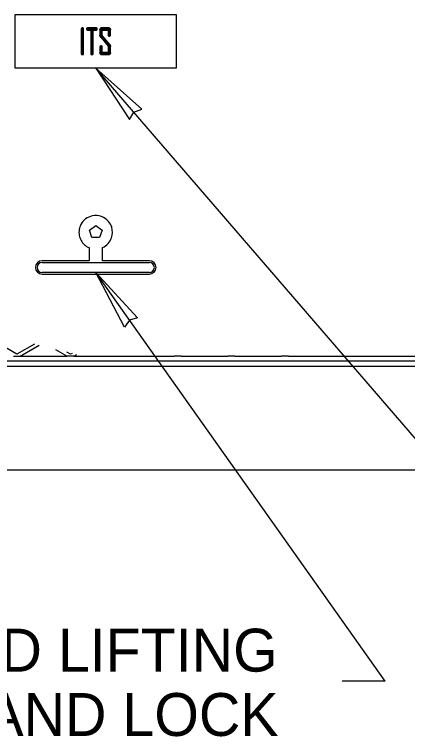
# Model space of a CAD drawing. Extents: x 99862 to 103151, y 100000 to 105076.
# Drawn here: x 100264.4 to 100411, y 100268.6 to 100538 of the extents above; entities that cross this region are included whole.
import ezdxf

# ---------------------------------------------------------------- set-up
doc = ezdxf.new("R2010")
doc.units = 0
for name, color, linetype in [('Level 12', 7, 'Continuous'), ('Level 15', 7, 'Continuous'), ('Level 20', 7, 'Continuous'), ('Level 3', 7, 'Continuous'), ('Level 4', 7, 'Continuous'), ('Level 5', 7, 'Continuous')]:
    doc.layers.add(name, color=color, linetype=linetype)

msp = doc.modelspace()

# ---------------------------------------------------------------- linework, layer by layer
at = {"layer": 'Level 12'}
for p, q in [((100289.27, 100532.65), (100289.59, 100532.65)), ((100289.27, 100532.65), (100289.27, 100523.3)), ((100289.59, 100532.96), (100289.59, 100532.65)), ((100289.85, 100532.96), (100289.59, 100532.96)), ((100289.85, 100532.65), (100289.59, 100532.65)), ((100289.59, 100532.65), (100289.59, 100523.3)), ((100289.85, 100532.96), (100289.85, 100532.65)), ((100289.85, 100532.65), (100290.16, 100532.65)), ((100289.85, 100523.3), (100289.85, 100532.65)), ((100290.16, 100523.3), (100290.16, 100532.65)), ((100291.27, 100532.65), (100291.58, 100532.65)), ((100291.27, 100532.65), (100291.27, 100532.49)), ((100291.27, 100532.49), (100291.58, 100532.49)), ((100294.95, 100532.96), (100291.58, 100532.96)), ((100291.58, 100532.65), (100291.58, 100532.96)), ((100294.95, 100532.65), (100291.58, 100532.65)), ((100291.58, 100532.65), (100291.58, 100532.49)), ((100291.58, 100532.49), (100293.14, 100532.49)), ((100291.58, 100532.18), (100291.58, 100532.49)), ((100291.58, 100532.18), (100292.82, 100532.18)), ((100292.82, 100532.18), (100293.14, 100532.49)), ((100292.82, 100532.18), (100292.82, 100523.3)), ((100293.14, 100532.49), (100293.14, 100523.3)), ((100293.4, 100532.49), (100293.71, 100532.18)), ((100293.4, 100532.49), (100294.95, 100532.49)), ((100293.4, 100523.3), (100293.4, 100532.49)), ((100293.71, 100532.18), (100294.95, 100532.18)), ((100293.71, 100523.3), (100293.71, 100532.18)), ((100294.95, 100532.65), (100294.95, 100532.96)), ((100294.95, 100532.65), (100295.26, 100532.65)), ((100294.95, 100532.49), (100294.95, 100532.65)), ((100294.95, 100532.49), (100295.26, 100532.49)), ((100294.95, 100532.18), (100294.95, 100532.49)), ((100295.26, 100532.49), (100295.26, 100532.65)), ((100296.26, 100532.22), (100296.26, 100530.23)), ((100296.26, 100532.22), (100296.57, 100532.22)), ((100296.47, 100532.76), (100296.69, 100532.54)), ((100296.57, 100532.22), (100296.57, 100530.23)), ((100297.15, 100532.18), (100296.84, 100532.49)), ((100296.84, 100529.96), (100296.84, 100532.49)), ((100296.84, 100532.49), (100299.61, 100532.49)), ((100297, 100532.65), (100297, 100532.96)), ((100299.45, 100532.96), (100297, 100532.96)), ((100299.45, 100532.65), (100297, 100532.65)), ((100297.15, 100530.08), (100297.15, 100532.18)), ((100297.15, 100532.18), (100299.3, 100532.18)), ((100299.3, 100532.18), (100299.61, 100532.49)), ((100299.3, 100532.18), (100299.3, 100530.25)), ((100299.45, 100532.65), (100299.45, 100532.96)), ((100299.61, 100532.49), (100299.61, 100530.25)), ((100299.98, 100532.76), (100299.76, 100532.54)), ((100299.88, 100532.22), (100300.19, 100532.22)), ((100299.88, 100530.25), (100299.88, 100532.22)), ((100300.19, 100530.25), (100300.19, 100532.22)), ((100296.26, 100530.23), (100296.57, 100530.23)), ((100296.55, 100529.48), (100296.79, 100529.67)), ((100296.55, 100529.48), (100299.3, 100526.15)), ((100296.79, 100529.67), (100299.61, 100526.26)), ((100297.15, 100530.08), (100296.84, 100529.96)), ((100299.67, 100526.55), (100296.84, 100529.96)), ((100299.92, 100526.75), (100297.15, 100530.08)), ((100299.3, 100530.25), (100299.61, 100530.25)), ((100299.61, 100529.94), (100299.61, 100530.25)), ((100299.61, 100530.25), (100299.88, 100530.25)), ((100299.61, 100529.94), (100299.88, 100529.94)), ((100299.88, 100529.94), (100299.88, 100530.25)), ((100299.88, 100530.25), (100300.19, 100530.25)), ((100296.26, 100525.91), (100296.26, 100523.72)), ((100296.26, 100525.91), (100296.57, 100525.91)), ((100296.84, 100526.22), (100296.57, 100526.22)), ((100296.57, 100525.91), (100296.57, 100526.22)), ((100296.57, 100525.91), (100296.57, 100523.72)), ((100296.84, 100525.91), (100296.57, 100525.91)), ((100296.84, 100525.91), (100296.84, 100526.22)), ((100296.84, 100525.91), (100297.15, 100525.91)), ((100296.84, 100523.46), (100296.84, 100525.91)), ((100297.15, 100523.77), (100297.15, 100525.91)), ((100299.61, 100526.26), (100299.3, 100526.15)), ((100299.3, 100526.15), (100299.3, 100523.77)), ((100299.61, 100526.26), (100299.61, 100523.46)), ((100299.88, 100526), (100300.19, 100526)), ((100299.88, 100523.72), (100299.88, 100526)), ((100300.19, 100523.72), (100300.19, 100526)), ((100289.27, 100523.3), (100289.59, 100523.3)), ((100289.59, 100523.3), (100289.85, 100523.3)), ((100289.59, 100523.3), (100289.59, 100522.99)), ((100289.85, 100523.3), (100290.16, 100523.3)), ((100289.85, 100523.3), (100289.85, 100522.99)), ((100292.82, 100523.3), (100293.14, 100523.3)), ((100293.14, 100522.99), (100293.14, 100523.3)), ((100293.14, 100523.3), (100293.4, 100523.3)), ((100293.4, 100523.3), (100293.71, 100523.3)), ((100293.4, 100522.99), (100293.4, 100523.3)), ((100296.26, 100523.72), (100296.57, 100523.72)), ((100296.69, 100523.41), (100296.47, 100523.19)), ((100297.15, 100523.77), (100296.84, 100523.46)), ((100299.61, 100523.46), (100296.84, 100523.46)), ((100297, 100522.99), (100297, 100523.3)), ((100297, 100523.3), (100299.45, 100523.3)), ((100299.3, 100523.77), (100297.15, 100523.77)), ((100299.3, 100523.77), (100299.61, 100523.46)), ((100299.45, 100522.99), (100299.45, 100523.3)), ((100299.76, 100523.41), (100299.98, 100523.19)), ((100299.88, 100523.72), (100300.19, 100523.72)), ((100289.59, 100522.99), (100289.85, 100522.99)), ((100293.14, 100522.99), (100293.4, 100522.99)), ((100297, 100522.99), (100299.45, 100522.99)), ((100292.34, 100457.5), (100294.69, 100459.21)), ((100294.69, 100459.21), (100297.05, 100457.5)), ((100293.24, 100454.73), (100292.34, 100457.5)), ((100297.05, 100457.5), (100296.15, 100454.73)), ((100296.15, 100454.73), (100293.24, 100454.73))]:
    msp.add_line(p, q, dxfattribs=at)
msp.add_lwpolyline([(100264.69, 100517.99), (100264.69, 100537.98), (100324.69, 100537.98), (100324.69, 100517.99), (100264.69, 100517.99)], dxfattribs=at)
for centre, start, end in [((100289.59, 100532.65), 90, 180), ((100289.85, 100532.65), 0, 90), ((100291.58, 100532.65), 90, 180), ((100291.58, 100532.49), 180, 270), ((100294.95, 100532.65), 0, 90), ((100294.95, 100532.49), 270, 0), ((100299.61, 100530.25), 180, 270), ((100299.88, 100530.25), 270, 0), ((100296.57, 100525.91), 90, 180), ((100296.84, 100525.91), 0, 90), ((100289.59, 100523.3), 180, 270), ((100289.85, 100523.3), 270, 0), ((100293.14, 100523.3), 180, 270), ((100293.4, 100523.3), 270, 0)]:
    msp.add_arc(centre, 0.312, start, end, dxfattribs=at)
msp.add_ellipse((100299.68, 100526.55), major_axis=(0.24, 0.2), ratio=0.002663, start_param=6.283185, end_param=7.853982, dxfattribs=at)
for points, degree in [([(100296.47, 100532.76), (100296.26, 100532.55), (100296.26, 100532.22)], 2), ([(100296.26, 100532.22), (100296.26, 100532.22), (100296.26, 100532.23), (100296.26, 100532.23), (100296.26, 100532.29), (100296.27, 100532.35), (100296.28, 100532.42), (100296.29, 100532.48), (100296.32, 100532.54), (100296.35, 100532.6), (100296.38, 100532.66), (100296.42, 100532.71), (100296.47, 100532.76)], 3), ([(100297, 100532.96), (100296.68, 100532.96), (100296.47, 100532.76)], 2), ([(100296.47, 100532.76), (100296.47, 100532.76), (100296.47, 100532.76), (100296.47, 100532.76), (100296.52, 100532.81), (100296.58, 100532.85), (100296.64, 100532.88), (100296.7, 100532.91), (100296.76, 100532.93), (100296.83, 100532.95), (100296.88, 100532.96), (100296.94, 100532.96), (100297, 100532.96)], 3), ([(100296.69, 100532.54), (100296.66, 100532.51), (100296.64, 100532.48), (100296.62, 100532.45), (100296.61, 100532.42), (100296.59, 100532.38), (100296.58, 100532.35), (100296.58, 100532.31), (100296.57, 100532.27), (100296.57, 100532.22)], 3), ([(100297, 100532.65), (100296.96, 100532.65), (100296.93, 100532.65), (100296.89, 100532.64), (100296.85, 100532.63), (100296.82, 100532.62), (100296.78, 100532.61), (100296.75, 100532.59), (100296.72, 100532.56), (100296.69, 100532.54)], 3), ([(100299.98, 100532.76), (100299.78, 100532.96), (100299.45, 100532.96)], 2), ([(100299.45, 100532.96), (100299.45, 100532.96), (100299.45, 100532.96), (100299.45, 100532.96), (100299.51, 100532.96), (100299.56, 100532.96), (100299.61, 100532.95), (100299.69, 100532.94), (100299.76, 100532.91), (100299.83, 100532.87), (100299.89, 100532.84), (100299.94, 100532.8), (100299.98, 100532.76)], 3), ([(100299.76, 100532.54), (100299.74, 100532.56), (100299.71, 100532.58), (100299.68, 100532.6), (100299.64, 100532.62), (100299.6, 100532.63), (100299.56, 100532.64), (100299.52, 100532.65), (100299.49, 100532.65), (100299.45, 100532.65)], 3), ([(100299.88, 100532.22), (100299.88, 100532.26), (100299.87, 100532.29), (100299.87, 100532.33), (100299.86, 100532.37), (100299.84, 100532.42), (100299.82, 100532.46), (100299.81, 100532.49), (100299.79, 100532.51), (100299.76, 100532.54)], 3), ([(100300.19, 100532.22), (100300.19, 100532.55), (100299.98, 100532.76)], 2), ([(100299.98, 100532.76), (100299.99, 100532.76), (100299.99, 100532.76), (100299.99, 100532.76), (100300.03, 100532.71), (100300.06, 100532.67), (100300.09, 100532.62), (100300.13, 100532.55), (100300.16, 100532.47), (100300.18, 100532.38), (100300.19, 100532.33), (100300.19, 100532.28), (100300.19, 100532.22)], 3), ([(100296.26, 100530.23), (100296.26, 100529.82), (100296.55, 100529.48)], 2), ([(100296.55, 100529.48), (100296.55, 100529.48), (100296.55, 100529.48), (100296.55, 100529.48), (100296.51, 100529.52), (100296.48, 100529.56), (100296.45, 100529.61), (100296.38, 100529.71), (100296.33, 100529.83), (100296.29, 100529.95), (100296.27, 100530.05), (100296.26, 100530.14), (100296.26, 100530.23)], 3), ([(100296.57, 100530.23), (100296.57, 100530.17), (100296.58, 100530.1), (100296.6, 100530.03), (100296.62, 100529.94), (100296.66, 100529.86), (100296.71, 100529.78), (100296.73, 100529.74), (100296.76, 100529.71), (100296.79, 100529.67)], 3), ([(100299.88, 100526), (100299.88, 100526.07), (100299.87, 100526.13), (100299.85, 100526.2), (100299.83, 100526.28), (100299.8, 100526.37), (100299.75, 100526.44), (100299.73, 100526.48), (100299.7, 100526.51), (100299.67, 100526.55)], 3), ([(100300.19, 100526), (100300.19, 100526.41), (100299.92, 100526.75)], 2), ([(100299.92, 100526.75), (100299.92, 100526.74), (100299.92, 100526.74), (100299.92, 100526.74), (100299.95, 100526.7), (100299.98, 100526.66), (100300.01, 100526.61), (100300.08, 100526.51), (100300.13, 100526.39), (100300.16, 100526.27), (100300.18, 100526.18), (100300.19, 100526.09), (100300.19, 100526)], 3), ([(100296.26, 100523.72), (100296.26, 100523.4), (100296.47, 100523.19)], 2), ([(100296.47, 100523.19), (100296.47, 100523.19), (100296.47, 100523.19), (100296.47, 100523.19), (100296.42, 100523.23), (100296.39, 100523.28), (100296.36, 100523.33), (100296.32, 100523.4), (100296.29, 100523.48), (100296.27, 100523.56), (100296.26, 100523.61), (100296.26, 100523.67), (100296.26, 100523.72)], 3), ([(100296.47, 100523.19), (100296.68, 100522.99), (100297, 100522.99)], 2), ([(100297, 100522.99), (100297, 100522.99), (100297, 100522.99), (100297, 100522.99), (100296.94, 100522.99), (100296.88, 100522.99), (100296.82, 100523), (100296.75, 100523.02), (100296.69, 100523.04), (100296.63, 100523.07), (100296.57, 100523.1), (100296.52, 100523.14), (100296.47, 100523.19)], 3), ([(100296.57, 100523.72), (100296.57, 100523.69), (100296.58, 100523.65), (100296.58, 100523.62), (100296.59, 100523.57), (100296.61, 100523.53), (100296.63, 100523.49), (100296.64, 100523.46), (100296.67, 100523.44), (100296.69, 100523.41)], 3), ([(100296.69, 100523.41), (100296.71, 100523.39), (100296.74, 100523.36), (100296.78, 100523.35), (100296.81, 100523.33), (100296.85, 100523.32), (100296.88, 100523.31), (100296.92, 100523.3), (100296.96, 100523.3), (100297, 100523.3)], 3), ([(100299.45, 100523.3), (100299.48, 100523.3), (100299.52, 100523.3), (100299.55, 100523.31), (100299.6, 100523.31), (100299.64, 100523.33), (100299.69, 100523.35), (100299.71, 100523.37), (100299.74, 100523.39), (100299.76, 100523.41)], 3), ([(100299.45, 100522.99), (100299.78, 100522.99), (100299.98, 100523.19)], 2), ([(100299.98, 100523.19), (100299.98, 100523.19), (100299.98, 100523.19), (100299.98, 100523.19), (100299.94, 100523.15), (100299.89, 100523.11), (100299.84, 100523.08), (100299.77, 100523.04), (100299.68, 100523.01), (100299.6, 100523), (100299.55, 100522.99), (100299.5, 100522.99), (100299.45, 100522.99)], 3), ([(100299.76, 100523.41), (100299.79, 100523.44), (100299.81, 100523.47), (100299.83, 100523.5), (100299.85, 100523.54), (100299.86, 100523.58), (100299.87, 100523.62), (100299.87, 100523.66), (100299.88, 100523.69), (100299.88, 100523.72)], 3), ([(100299.98, 100523.19), (100300.19, 100523.4), (100300.19, 100523.72)], 2), ([(100300.19, 100523.72), (100300.19, 100523.72), (100300.19, 100523.72), (100300.19, 100523.72), (100300.19, 100523.67), (100300.19, 100523.62), (100300.18, 100523.57), (100300.16, 100523.49), (100300.14, 100523.42), (100300.1, 100523.35), (100300.07, 100523.29), (100300.03, 100523.24), (100299.98, 100523.19)], 3)]:
    msp.add_open_spline(points, degree=degree, dxfattribs=at)
at = {"layer": 'Level 15'}
for p, q in [((100491.85, 100289.35), (100294.69, 100517.99)), ((100402.64, 100289.35), (100294.69, 100441.73)), ((100402.64, 100289.35), (100386.64, 100289.35))]:
    msp.add_line(p, q, dxfattribs=at)
for points in [[(100294.69, 100517.99), (100307.34, 100498.74), (100308.91, 100501.49), (100311.86, 100502.64)], [(100294.69, 100441.73), (100310.32, 100424.83), (100307.28, 100423.97), (100305.45, 100421.38)]]:
    msp.add_lwpolyline(points, close=True, dxfattribs=at)
at = {"layer": 'Level 3'}
for p, q in [((100479.07, 100406.73), (100110.32, 100406.73)), ((100514.69, 100367.98), (100074.69, 100367.98))]:
    msp.add_line(p, q, dxfattribs=at)
at = {"layer": 'Level 4'}
msp.add_line((100477.19, 100408.61), (100112.19, 100408.61), dxfattribs=at)
at = {"layer": 'Level 5'}
for p, q in [((100292.19, 100451.01), (100292.19, 100449.86)), ((100297.19, 100450.54), (100297.19, 100451.01)), ((100297.19, 100449.1), (100297.19, 100450.54)), ((100292.19, 100449.86), (100292.19, 100448.41)), ((100292.19, 100448.41), (100292.19, 100446.11)), ((100297.19, 100446.11), (100297.19, 100449.1)), ((100282.36, 100446.11), (100274.69, 100446.11)), ((100274.69, 100445.48), (100282.19, 100445.48)), ((100282.19, 100445.48), (100307.19, 100445.48)), ((100284.86, 100446.11), (100282.36, 100446.11)), ((100285.7, 100446.11), (100284.86, 100446.11)), ((100288.2, 100446.11), (100285.7, 100446.11)), ((100292.19, 100446.11), (100288.2, 100446.11)), ((100302.36, 100446.11), (100297.19, 100446.11)), ((100304.86, 100446.11), (100302.36, 100446.11)), ((100305.7, 100446.11), (100304.86, 100446.11)), ((100308.2, 100446.11), (100305.7, 100446.11)), ((100307.19, 100445.48), (100314.69, 100445.48)), ((100314.69, 100446.11), (100308.2, 100446.11)), ((100282.19, 100441.73), (100274.69, 100441.73)), ((100274.69, 100441.11), (100277.04, 100441.11)), ((100277.04, 100441.11), (100279.54, 100441.11)), ((100279.54, 100441.11), (100291.02, 100441.11)), ((100307.19, 100441.73), (100282.19, 100441.73)), ((100291.02, 100441.11), (100293.52, 100441.11)), ((100293.52, 100441.11), (100297.04, 100441.11)), ((100297.04, 100441.11), (100299.54, 100441.11)), ((100299.54, 100441.11), (100311.02, 100441.11)), ((100314.69, 100441.73), (100307.19, 100441.73)), ((100311.02, 100441.11), (100313.52, 100441.11)), ((100313.52, 100441.11), (100314.69, 100441.11)), ((100265.28, 100411.23), (100256.53, 100416.28)), ((100271.86, 100415.03), (100265.28, 100411.23)), ((100266.53, 100410.51), (100273.57, 100414.57)), ((100279.66, 100413.03), (100284.03, 100410.51)), ((100264, 100410.48), (100266.57, 100410.48)), ((100266.57, 100410.48), (100266.53, 100410.51)), ((100266.57, 100410.48), (100284, 100410.48)), ((100285.28, 100411.23), (100283.9, 100412.02)), ((100284.03, 100410.51), (100284, 100410.48)), ((100286.57, 100410.48), (100284, 100410.48)), ((100285.88, 100411.57), (100285.28, 100411.23)), ((100286.53, 100410.51), (100287.69, 100411.17)), ((100286.57, 100410.48), (100286.53, 100410.51)), ((100286.57, 100410.48), (100304, 100410.48)), ((100304.03, 100410.51), (100304, 100410.48)), ((100304, 100410.48), (100306.57, 100410.48)), ((100306.57, 100410.48), (100306.53, 100410.51)), ((100306.57, 100410.48), (100324, 100410.48)), ((100324.03, 100410.51), (100324, 100410.48)), ((100326.57, 100410.48), (100324, 100410.48)), ((100326.57, 100410.48), (100326.53, 100410.51)), ((100326.57, 100410.48), (100344, 100410.48)), ((100344.03, 100410.51), (100344, 100410.48)), ((100346.57, 100410.48), (100344, 100410.48)), ((100346.57, 100410.48), (100346.53, 100410.51)), ((100346.57, 100410.48), (100364, 100410.48)), ((100364.03, 100410.51), (100364, 100410.48)), ((100366.57, 100410.48), (100364, 100410.48)), ((100366.57, 100410.48), (100366.53, 100410.51)), ((100366.57, 100410.48), (100382.75, 100410.48)), ((100382.75, 100410.48), (100446.57, 100410.48))]:
    msp.add_line(p, q, dxfattribs=at)
for centre, radius, start, end in [((100294.69, 100456.73), 6.25, 102.1385, 152.0969), ((100294.69, 100456.73), 6.25, 70.3271, 102.1385), ((100294.69, 100456.73), 6.25, 40.3092, 70.3271), ((100294.69, 100456.73), 6.25, 152.0969, 169.6729), ((100294.69, 100456.73), 6.25, 17.8615, 40.3092), ((100294.69, 100456.73), 6.25, 341.1622, 17.8615), ((100294.69, 100456.73), 6.25, 169.6729, 191.1837), ((100294.69, 100456.73), 6.25, 191.1837, 209.1458), ((100294.69, 100456.73), 6.25, 209.1458, 246.4218), ((100294.69, 100456.73), 6.25, 317.6646, 341.1622), ((100294.69, 100456.73), 6.25, 293.5782, 317.6646), ((100274.69, 100443.61), 2.5, 90, 270), ((100274.69, 100443.61), 1.88, 90, 270), ((100314.69, 100443.61), 2.5, 270, 90), ((100314.69, 100443.61), 1.88, 270, 90)]:
    msp.add_arc(centre, radius, start, end, dxfattribs=at)

# ---------------------------------------------------------------- texts
at = {"layer": 'Level 20'}
for s, p in [('RECESSED LIFTING', (100156.92, 100292.86)), ('RING AND LOCK', (100194.09, 100268.86))]:
    msp.add_text(s, height=16, rotation=360, dxfattribs=at).set_placement(p)

doc.saveas('drawing.dxf')
